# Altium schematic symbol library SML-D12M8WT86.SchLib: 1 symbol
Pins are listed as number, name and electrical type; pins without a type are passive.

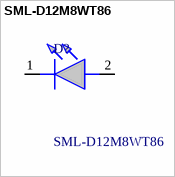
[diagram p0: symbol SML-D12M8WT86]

## SML-D12M8WT86
designator D?
EXCELED&trade; series chip LED: ROHM's chip LED lineup consists of standard type,top-view type, side-view type and reverse-mount type.; Manufacturer_Name: ROHM Semiconductor; Geometry.Height: 1.5mm
footprint LEDM1620X150N
pins: 1 K, 2 A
